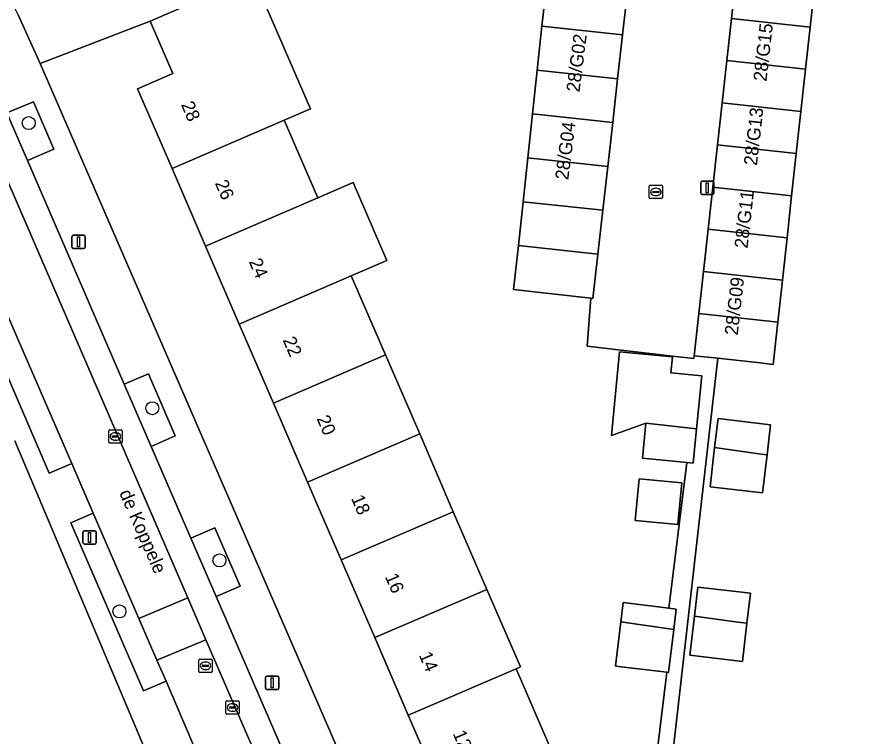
# Model space of a CAD drawing. Extents: x 162026 to 163502, y 387295 to 388169.
# Drawn here: x 162167.8 to 162230.9, y 387554 to 387608.3 of the extents above; entities that cross this region are included whole.
import ezdxf

# ---------------------------------------------------------------- set-up
doc = ezdxf.new("R2010")
doc.units = 0
for name, color, linetype in [('IMGEO_Boom', 7, 'Continuous'), ('IMGEO_Erf', 7, 'Continuous'), ('IMGEO_Groenvoorziening', 7, 'Continuous'), ('IMGEO_Kolk', 7, 'Continuous'), ('IMGEO_Lichtmast', 7, 'Continuous'), ('IMGEO_Openbare_ruimte_label', 7, 'Continuous'), ('IMGEO_Pand', 7, 'Continuous'), ('IMGEO_Pand_nummerreeks', 7, 'Continuous'), ('IMGEO_Parkeervlak_open', 7, 'Continuous'), ('IMGEO_Rijbaan_lokaal_open', 7, 'Continuous'), ('IMGEO_Rioolput', 7, 'Continuous'), ('IMGEO_Voetpad_open', 7, 'Continuous')]:
    doc.layers.add(name, color=color, linetype=linetype)

msp = doc.modelspace()

# ---------------------------------------------------------------- linework, layer by layer
at = {"layer": 'IMGEO_Boom'}
for centre in [(162168.747, 387600.231), (162178.065, 387578.73), (162183.126, 387567.244), (162175.583, 387563.398)]:
    msp.add_circle(centre, 0.489, dxfattribs=at)
at = {"layer": 'IMGEO_Erf'}
for points in [[(162240.54, 387631.778), (162230.472, 387632.88), (162230.124, 387629.722), (162229.773, 387626.543), (162229.422, 387623.364), (162229.071, 387620.185), (162228.72, 387617.006), (162228.37, 387613.827), (162228.019, 387610.647), (162227.668, 387607.468), (162227.317, 387604.289), (162226.966, 387601.11), (162226.616, 387597.931), (162226.265, 387594.752), (162225.914, 387591.573), (162225.563, 387588.394), (162225.212, 387585.214), (162224.861, 387582.031), (162223.896, 387582.138), (162220.71, 387582.491), (162216.94, 387549.426)], [(162185.674, 387611.291), (162189.987, 387601.306), (162188.001, 387600.448), (162190.532, 387594.591), (162193.203, 387595.743), (162195.737, 387589.877), (162193.066, 387588.725), (162195.647, 387582.748), (162198.221, 387576.79), (162200.755, 387570.924), (162203.289, 387565.057), (162205.815, 387559.209), (162205.496, 387559.072), (162210.608, 387547.253)], [(162215.593, 387548.453), (162216.856, 387558.813), (162212.99, 387559.284), (162213.396, 387562.616), (162213.573, 387564.068), (162217.015, 387563.648), (162218.354, 387574.629), (162215.021, 387574.957), (162215.281, 387577.595), (162212.679, 387576.674), (162213.296, 387582.99), (162217.277, 387582.6), (162217.284, 387582.658), (162210.842, 387583.401), (162211.127, 387587.022), (162205.304, 387587.68), (162205.66, 387590.99), (162206.016, 387594.299), (162206.372, 387597.609), (162206.727, 387600.919), (162207.083, 387604.229), (162207.439, 387607.538), (162207.795, 387610.848)], [(162199.955, 387549.558), (162197.353, 387555.582), (162194.827, 387561.43), (162192.297, 387567.287), (162189.763, 387573.153), (162187.193, 387579.101), (162184.612, 387585.078), (162182.078, 387590.944), (162179.548, 387596.801), (162176.945, 387602.826), (162179.598, 387603.972), (162177.889, 387607.929), (162169.617, 387604.73), (162206.97, 387518.594)], [(162192.733, 387518.666), (162181.749, 387542.942), (162167.692, 387576.257)]]:
    msp.add_lwpolyline(points, dxfattribs=at)
for points in [[(162224.672, 387577.479), (162224.406, 387575.221), (162224.067, 387572.335), (162220.109, 387572.801), (162220.457, 387575.761), (162220.714, 387577.945)], [(162214.772, 387573.405), (162217.984, 387573.089), (162217.675, 387569.947), (162214.462, 387570.263)], [(162223.159, 387564.771), (162222.894, 387562.52), (162222.554, 387559.627), (162218.596, 387560.092), (162218.944, 387563.05), (162219.201, 387565.236)]]:
    msp.add_lwpolyline(points, close=True, dxfattribs=at)
at = {"layer": 'IMGEO_Groenvoorziening'}
for points in [[(162167.091, 387600.998), (162168.662, 387597.412), (162170.641, 387598.257), (162169.112, 387601.843)], [(162167.139, 387585.739), (162165.454, 387585.008), (162170.297, 387573.838), (162171.986, 387574.558)], [(162175.938, 387580.549), (162177.973, 387575.852), (162179.793, 387576.634), (162177.764, 387581.326)], [(162173.611, 387570.804), (162171.912, 387570.09), (162177.391, 387557.416), (162179.11, 387558.145), (162178.416, 387559.712), (162177.044, 387562.862)], [(162180.971, 387568.927), (162182.887, 387564.514), (162184.692, 387565.294), (162182.789, 387569.707)]]:
    msp.add_lwpolyline(points, close=True, dxfattribs=at)
at = {"layer": 'IMGEO_Kolk'}
for p, q in [((162215.53, 387594.615), (162215.53, 387595.467)), ((162215.605, 387595.541), (162216.457, 387595.541)), ((162216.018, 387595.321), (162216.043, 387595.321)), ((162216.531, 387595.467), (162216.531, 387594.615)), ((162216.457, 387594.541), (162215.605, 387594.541)), ((162215.789, 387595.035), (162215.789, 387595.047)), ((162216.227, 387594.998), (162215.829, 387594.998)), ((162215.832, 387595.084), (162216.23, 387595.084)), ((162216.041, 387594.761), (162216.016, 387594.761)), ((162216.273, 387595.047), (162216.273, 387595.035)), ((162174.783, 387576.171), (162174.783, 387577.023)), ((162174.858, 387577.097), (162175.71, 387577.097)), ((162175.271, 387576.877), (162175.296, 387576.877)), ((162175.784, 387577.023), (162175.784, 387576.171)), ((162175.042, 387576.591), (162175.042, 387576.603)), ((162175.48, 387576.554), (162175.082, 387576.554)), ((162175.085, 387576.64), (162175.483, 387576.64)), ((162175.294, 387576.317), (162175.269, 387576.317)), ((162175.526, 387576.603), (162175.526, 387576.591)), ((162175.71, 387576.097), (162174.858, 387576.097)), ((162183.616, 387555.725), (162183.616, 387556.577)), ((162183.691, 387556.651), (162184.543, 387556.651)), ((162183.875, 387556.145), (162183.875, 387556.157)), ((162184.313, 387556.108), (162183.915, 387556.108)), ((162183.918, 387556.194), (162184.316, 387556.194)), ((162184.104, 387556.431), (162184.129, 387556.431)), ((162184.359, 387556.157), (162184.359, 387556.145)), ((162184.617, 387556.577), (162184.617, 387555.725)), ((162184.543, 387555.651), (162183.691, 387555.651)), ((162184.127, 387555.871), (162184.102, 387555.871))]:
    msp.add_line(p, q, dxfattribs=at)
for points in [[(162215.53, 387594.615), (162215.53, 387595.467)], [(162215.605, 387595.541), (162216.457, 387595.541)], [(162216.531, 387595.467), (162216.531, 387594.615)], [(162216.457, 387594.541), (162215.605, 387594.541)], [(162174.783, 387576.171), (162174.783, 387577.023)], [(162174.858, 387577.097), (162175.71, 387577.097)], [(162175.784, 387577.023), (162175.784, 387576.171)], [(162175.71, 387576.097), (162174.858, 387576.097)], [(162183.616, 387555.725), (162183.616, 387556.577)], [(162183.691, 387556.651), (162184.543, 387556.651)], [(162184.617, 387556.577), (162184.617, 387555.725)], [(162184.543, 387555.651), (162183.691, 387555.651)]]:
    msp.add_lwpolyline(points, dxfattribs=at)
for centre, radius, start, end in [((162215.607, 387595.465), 0.0765, 91.55205, 178.44795), ((162215.607, 387595.465), 0.0765, 91.55205, 178.44795), ((162216.455, 387595.465), 0.0765, 1.55205, 88.44795), ((162216.455, 387595.465), 0.0765, 1.55205, 88.44795), ((162215.607, 387594.617), 0.0765, 181.55205, 268.44795), ((162215.607, 387594.617), 0.0765, 181.55205, 268.44795), ((162215.829, 387595.044), 0.0403, 85.87752, 175.75265), ((162215.826, 387595.034), 0.0366, 178.93798, 274.71019), ((162216.23, 387595.041), 0.043, 264.86636, 352.45326), ((162216.234, 387595.046), 0.0386, 1.73085, 96.63898), ((162216.455, 387594.617), 0.0765, 271.55205, 358.44795), ((162216.455, 387594.617), 0.0765, 271.55205, 358.44795), ((162174.86, 387577.021), 0.0765, 91.55205, 178.44795), ((162174.86, 387577.021), 0.0765, 91.55205, 178.44795), ((162175.708, 387577.021), 0.0765, 1.55205, 88.44795), ((162175.708, 387577.021), 0.0765, 1.55205, 88.44795), ((162175.082, 387576.6), 0.0403, 85.87752, 175.75265), ((162175.079, 387576.59), 0.0366, 178.93798, 274.71019), ((162175.483, 387576.597), 0.043, 264.86636, 352.45326), ((162175.487, 387576.602), 0.0386, 1.73085, 96.63898), ((162174.86, 387576.173), 0.0765, 181.55205, 268.44795), ((162174.86, 387576.173), 0.0765, 181.55205, 268.44795), ((162175.708, 387576.173), 0.0765, 271.55205, 358.44795), ((162175.708, 387576.173), 0.0765, 271.55205, 358.44795), ((162183.693, 387556.575), 0.0765, 91.55205, 178.44795), ((162183.693, 387556.575), 0.0765, 91.55205, 178.44795), ((162183.915, 387556.154), 0.0403, 85.87752, 175.75265), ((162183.912, 387556.144), 0.0366, 178.93798, 274.71019), ((162184.316, 387556.151), 0.043, 264.86636, 352.45326), ((162184.32, 387556.156), 0.0386, 1.73085, 96.63898), ((162184.541, 387556.575), 0.0765, 1.55205, 88.44795), ((162184.541, 387556.575), 0.0765, 1.55205, 88.44795), ((162183.693, 387555.727), 0.0765, 181.55205, 268.44795), ((162183.693, 387555.727), 0.0765, 181.55205, 268.44795), ((162184.541, 387555.727), 0.0765, 271.55205, 358.44795), ((162184.541, 387555.727), 0.0765, 271.55205, 358.44795)]:
    msp.add_arc(centre, radius, start, end, dxfattribs=at)
for centre, major_axis, ratio, start_param, end_param in [((162216.017, 387595.041), (-0.387, 0.002), 0.722429, 4.712389, 7.853982), ((162216.042, 387595.041), (-0.39, 0.002), 0.717154, 1.570796, 4.712389), ((162175.27, 387576.597), (-0.387, 0.002), 0.722429, 4.712389, 7.853982), ((162175.295, 387576.597), (-0.39, 0.002), 0.717154, 1.570796, 4.712389), ((162184.103, 387556.151), (-0.387, 0.002), 0.722429, 4.712389, 7.853982), ((162184.128, 387556.151), (-0.39, 0.002), 0.717154, 1.570796, 4.712389)]:
    msp.add_ellipse(centre, major_axis=major_axis, ratio=ratio, start_param=start_param, end_param=end_param, dxfattribs=at)
at = {"layer": 'IMGEO_Lichtmast'}
for p, q in [((162219.509, 387595.854), (162220.299, 387595.854)), ((162220.299, 387595.854), (162219.509, 387595.854)), ((162219.409, 387594.954), (162219.409, 387595.754)), ((162219.409, 387595.754), (162219.409, 387594.954)), ((162220.399, 387595.754), (162220.399, 387594.954)), ((162220.399, 387594.954), (162220.399, 387595.754)), ((162220.299, 387594.854), (162219.509, 387594.854)), ((162219.509, 387594.854), (162220.299, 387594.854)), ((162172.006, 387590.877), (162172.006, 387591.677)), ((162172.006, 387591.677), (162172.006, 387590.877)), ((162172.106, 387591.777), (162172.896, 387591.777)), ((162172.896, 387591.777), (162172.106, 387591.777)), ((162172.996, 387591.677), (162172.996, 387590.877)), ((162172.996, 387590.877), (162172.996, 387591.677)), ((162172.896, 387590.777), (162172.106, 387590.777)), ((162172.106, 387590.777), (162172.896, 387590.777)), ((162172.834, 387568.582), (162172.834, 387569.382)), ((162172.834, 387569.382), (162172.834, 387568.582)), ((162172.934, 387569.482), (162173.724, 387569.482)), ((162173.724, 387569.482), (162172.934, 387569.482)), ((162173.824, 387569.382), (162173.824, 387568.582)), ((162173.824, 387568.582), (162173.824, 387569.382)), ((162173.724, 387568.482), (162172.934, 387568.482)), ((162172.934, 387568.482), (162173.724, 387568.482)), ((162186.604, 387557.617), (162186.604, 387558.417)), ((162186.604, 387558.417), (162186.604, 387557.617)), ((162186.704, 387558.517), (162187.494, 387558.517)), ((162187.494, 387558.517), (162186.704, 387558.517)), ((162187.594, 387558.417), (162187.594, 387557.617)), ((162187.594, 387557.617), (162187.594, 387558.417)), ((162187.494, 387557.517), (162186.704, 387557.517)), ((162186.704, 387557.517), (162187.494, 387557.517))]:
    msp.add_line(p, q, dxfattribs=at)
for points in [[(162219.829, 387595.729), (162219.979, 387595.729), (162219.979, 387594.979), (162219.829, 387594.979), (162219.829, 387595.729)], [(162172.426, 387591.652), (162172.576, 387591.652), (162172.576, 387590.902), (162172.426, 387590.902), (162172.426, 387591.652)], [(162173.254, 387569.357), (162173.404, 387569.357), (162173.404, 387568.607), (162173.254, 387568.607), (162173.254, 387569.357)], [(162187.024, 387558.392), (162187.174, 387558.392), (162187.174, 387557.642), (162187.024, 387557.642), (162187.024, 387558.392)]]:
    msp.add_lwpolyline(points, dxfattribs=at)
for centre, start, end in [((162219.509, 387595.754), 90, 180), ((162219.509, 387595.754), 90, 180), ((162220.299, 387595.754), 0, 90), ((162220.299, 387595.754), 360, 90), ((162219.509, 387594.954), 180, 270), ((162219.509, 387594.954), 180, 270), ((162220.299, 387594.954), 270, 0), ((162220.299, 387594.954), 270, 0), ((162172.106, 387591.677), 90, 180), ((162172.106, 387591.677), 90, 180), ((162172.896, 387591.677), 0, 90), ((162172.896, 387591.677), 360, 90), ((162172.106, 387590.877), 180, 270), ((162172.106, 387590.877), 180, 270), ((162172.896, 387590.877), 270, 0), ((162172.896, 387590.877), 270, 0), ((162172.934, 387569.382), 90, 180), ((162172.934, 387569.382), 90, 180), ((162173.724, 387569.382), 0, 90), ((162173.724, 387569.382), 360, 90), ((162172.934, 387568.582), 180, 270), ((162172.934, 387568.582), 180, 270), ((162173.724, 387568.582), 270, 0), ((162173.724, 387568.582), 270, 0), ((162186.704, 387558.417), 90, 180), ((162186.704, 387558.417), 90, 180), ((162187.494, 387558.417), 0, 90), ((162187.494, 387558.417), 360, 90), ((162186.704, 387557.617), 180, 270), ((162186.704, 387557.617), 180, 270), ((162187.494, 387557.617), 270, 0), ((162187.494, 387557.617), 270, 0)]:
    msp.add_arc(centre, 0.1, start, end, dxfattribs=at)
at = {"layer": 'IMGEO_Pand'}
for points in [[(162177.889, 387607.929), (162179.598, 387603.972), (162176.945, 387602.826), (162179.548, 387596.801), (162188.001, 387600.448), (162189.987, 387601.306), (162185.674, 387611.291)], [(162221.722, 387608.122), (162227.668, 387607.468), (162228.019, 387610.647), (162222.072, 387611.301)], [(162213.89, 387610.18), (162207.795, 387610.848), (162207.439, 387607.538), (162213.518, 387606.885)], [(162221.373, 387604.943), (162227.317, 387604.289), (162227.668, 387607.468), (162221.722, 387608.122)], [(162213.518, 387606.885), (162207.439, 387607.538), (162207.083, 387604.229), (162213.144, 387603.577)], [(162221.023, 387601.764), (162226.966, 387601.11), (162227.317, 387604.289), (162221.373, 387604.943)], [(162213.144, 387603.577), (162207.083, 387604.229), (162206.727, 387600.919), (162212.771, 387600.269)], [(162220.674, 387598.584), (162226.616, 387597.931), (162226.966, 387601.11), (162221.023, 387601.764)], [(162212.771, 387600.269), (162206.727, 387600.919), (162206.372, 387597.609), (162212.397, 387596.961)], [(162179.548, 387596.801), (162182.078, 387590.944), (162190.532, 387594.591), (162188.001, 387600.448)], [(162220.324, 387595.405), (162226.265, 387594.752), (162226.616, 387597.931), (162220.674, 387598.584)], [(162212.397, 387596.961), (162206.372, 387597.609), (162206.016, 387594.299), (162212.024, 387593.653)], [(162190.532, 387594.591), (162182.078, 387590.944), (162184.612, 387585.078), (162193.066, 387588.725), (162195.737, 387589.877), (162193.203, 387595.743)], [(162219.975, 387592.226), (162225.914, 387591.573), (162226.265, 387594.752), (162220.324, 387595.405)], [(162212.024, 387593.653), (162206.016, 387594.299), (162205.66, 387590.99), (162211.65, 387590.346)], [(162219.625, 387589.046), (162225.563, 387588.394), (162225.914, 387591.573), (162219.975, 387592.226)], [(162211.273, 387587.006), (162211.65, 387590.346), (162205.66, 387590.99), (162205.304, 387587.68), (162211.127, 387587.022)], [(162219.276, 387585.867), (162225.212, 387585.214), (162225.563, 387588.394), (162219.625, 387589.046)], [(162184.612, 387585.078), (162187.193, 387579.101), (162195.647, 387582.748), (162193.066, 387588.725)], [(162225.212, 387585.214), (162219.276, 387585.867), (162218.926, 387582.688), (162220.71, 387582.491), (162223.896, 387582.138), (162224.861, 387582.031)], [(162187.193, 387579.101), (162189.763, 387573.153), (162198.221, 387576.79), (162195.647, 387582.748)], [(162219.086, 387577.164), (162219.48, 387581.179), (162217.161, 387581.407), (162217.277, 387582.6), (162213.296, 387582.99), (162212.679, 387576.674), (162215.281, 387577.595)], [(162219.086, 387577.164), (162215.281, 387577.595), (162215.021, 387574.957), (162218.354, 387574.629), (162218.832, 387574.582)], [(162224.406, 387575.221), (162224.672, 387577.479), (162220.714, 387577.945), (162220.457, 387575.761), (162223.957, 387575.269)], [(162200.755, 387570.924), (162198.221, 387576.79), (162189.763, 387573.153), (162192.297, 387567.287)], [(162223.957, 387575.269), (162220.457, 387575.761), (162220.109, 387572.801), (162224.067, 387572.335), (162224.406, 387575.221)], [(162214.462, 387570.263), (162217.675, 387569.947), (162217.984, 387573.089), (162214.772, 387573.405)], [(162192.297, 387567.287), (162194.827, 387561.43), (162203.289, 387565.057), (162200.755, 387570.924)], [(162205.815, 387559.209), (162203.289, 387565.057), (162194.827, 387561.43), (162197.353, 387555.582), (162205.496, 387559.072)], [(162222.894, 387562.52), (162223.159, 387564.771), (162219.201, 387565.236), (162218.944, 387563.05), (162222.207, 387562.599)], [(162217.567, 387563.581), (162217.015, 387563.648), (162213.573, 387564.068), (162213.396, 387562.616), (162217.38, 387562.043)], [(162222.207, 387562.599), (162218.944, 387563.05), (162218.596, 387560.092), (162222.554, 387559.627), (162222.894, 387562.52)], [(162217.38, 387562.043), (162213.396, 387562.616), (162212.99, 387559.284), (162216.856, 387558.813), (162216.985, 387558.797)], [(162205.496, 387559.072), (162197.353, 387555.582), (162199.955, 387549.558), (162200.323, 387549.715), (162202.279, 387545.186), (162209.913, 387547.081), (162210.608, 387547.253)]]:
    msp.add_lwpolyline(points, close=True, dxfattribs=at)
at = {"layer": 'IMGEO_Parkeervlak_open'}
msp.add_lwpolyline([(162182.887, 387564.514), (162180.971, 387568.927), (162177.973, 387575.852), (162175.938, 387580.549), (162168.662, 387597.412), (162167.091, 387600.998), (162167.011, 387601.185), (162165.168, 387600.429), (162180.74, 387564.422), (162182.107, 387561.26), (162188.57, 387546.317), (162190.414, 387547.086), (162188.504, 387551.502)], close=True, dxfattribs=at)
at = {"layer": 'IMGEO_Rijbaan_lokaal_open'}
for points in [[(162167.945, 387608.39), (162169.617, 387604.73), (162177.889, 387607.929), (162185.674, 387611.291)], [(162213.89, 387610.18), (162213.518, 387606.885), (162213.144, 387603.577), (162212.771, 387600.269), (162212.397, 387596.961), (162212.024, 387593.653), (162211.65, 387590.346), (162211.273, 387587.006), (162211.127, 387587.022), (162210.842, 387583.401), (162217.284, 387582.658), (162218.894, 387582.472), (162218.926, 387582.688), (162219.276, 387585.867), (162219.625, 387589.046), (162219.975, 387592.226), (162220.324, 387595.405), (162220.674, 387598.584), (162221.023, 387601.764), (162221.373, 387604.943), (162221.722, 387608.122), (162222.072, 387611.301)], [(162157.496, 387608.095), (162161.151, 387599.629), (162163.025, 387595.286), (162167.139, 387585.739), (162171.986, 387574.558), (162173.611, 387570.804), (162177.044, 387562.862), (162180.74, 387564.422), (162165.168, 387600.429), (162161.658, 387608.545)], [(162202.905, 387512.975), (162201.516, 387516.321), (162199.227, 387521.644), (162192.35, 387537.558), (162188.57, 387546.317), (162182.107, 387561.26), (162178.416, 387559.712), (162179.11, 387558.145), (162181.87, 387551.664), (162188.019, 387537.445), (162191.081, 387530.363), (162197.664, 387515.178), (162197.789, 387514.889), (162198.944, 387512.277)]]:
    msp.add_lwpolyline(points, dxfattribs=at)
msp.add_lwpolyline([(162180.74, 387564.422), (162177.044, 387562.862), (162178.416, 387559.712), (162182.107, 387561.26)], close=True, dxfattribs=at)
at = {"layer": 'IMGEO_Rioolput'}
for p, q in [((162181.572, 387558.875), (162181.572, 387559.727)), ((162181.647, 387559.801), (162182.499, 387559.801)), ((162181.831, 387559.295), (162181.831, 387559.307)), ((162182.269, 387559.258), (162181.871, 387559.258)), ((162181.874, 387559.344), (162182.272, 387559.344)), ((162182.06, 387559.581), (162182.085, 387559.581)), ((162182.315, 387559.307), (162182.315, 387559.295)), ((162182.573, 387559.727), (162182.573, 387558.875)), ((162182.499, 387558.801), (162181.647, 387558.801)), ((162182.083, 387559.021), (162182.058, 387559.021))]:
    msp.add_line(p, q, dxfattribs=at)
for points in [[(162181.572, 387558.875), (162181.572, 387559.727)], [(162181.647, 387559.801), (162182.499, 387559.801)], [(162182.573, 387559.727), (162182.573, 387558.875)], [(162182.499, 387558.801), (162181.647, 387558.801)]]:
    msp.add_lwpolyline(points, dxfattribs=at)
for centre, radius, start, end in [((162181.649, 387559.725), 0.0765, 91.55205, 178.44795), ((162181.649, 387559.725), 0.0765, 91.55205, 178.44795), ((162181.871, 387559.304), 0.0403, 85.87752, 175.75265), ((162181.868, 387559.294), 0.0366, 178.93798, 274.71019), ((162182.272, 387559.301), 0.043, 264.86636, 352.45326), ((162182.276, 387559.306), 0.0386, 1.73085, 96.63898), ((162182.497, 387559.725), 0.0765, 1.55205, 88.44795), ((162182.497, 387559.725), 0.0765, 1.55205, 88.44795), ((162181.649, 387558.877), 0.0765, 181.55205, 268.44795), ((162181.649, 387558.877), 0.0765, 181.55205, 268.44795), ((162182.497, 387558.877), 0.0765, 271.55205, 358.44795), ((162182.497, 387558.877), 0.0765, 271.55205, 358.44795)]:
    msp.add_arc(centre, radius, start, end, dxfattribs=at)
for centre, major_axis, ratio, start_param, end_param in [((162182.059, 387559.301), (-0.387, 0.002), 0.722429, 4.712389, 7.853982), ((162182.084, 387559.301), (-0.39, 0.002), 0.717154, 1.570796, 4.712389)]:
    msp.add_ellipse(centre, major_axis=major_axis, ratio=ratio, start_param=start_param, end_param=end_param, dxfattribs=at)
at = {"layer": 'IMGEO_Voetpad_open'}
for points in [[(162206.97, 387518.594), (162169.617, 387604.73), (162167.945, 387608.39), (162167.679, 387608.941), (162167.267, 387609.969), (162166.949, 387611.031), (162166.875, 387611.347), (162166.727, 387612.116), (162166.603, 387613.218), (162166.477, 387613.998), (162166.652, 387615.431), (162167.307, 387621.991), (162166.913, 387622.036), (162167.629, 387628.415)], [(162163.509, 387609.313), (162167.011, 387601.185), (162167.091, 387600.998), (162169.112, 387601.843), (162170.641, 387598.257), (162168.662, 387597.412), (162175.938, 387580.549), (162177.764, 387581.326), (162179.793, 387576.634), (162177.973, 387575.852), (162180.971, 387568.927), (162182.789, 387569.707), (162184.692, 387565.294), (162182.887, 387564.514), (162188.504, 387551.502)], [(162179.11, 387558.145), (162177.391, 387557.416), (162171.912, 387570.09), (162173.611, 387570.804), (162171.986, 387574.558), (162170.297, 387573.838), (162165.454, 387585.008), (162167.139, 387585.739), (162163.025, 387595.286), (162161.041, 387594.389), (162159.155, 387598.767), (162161.151, 387599.629), (162157.496, 387608.095)], [(162216.94, 387549.426), (162220.71, 387582.491), (162218.926, 387582.688), (162218.894, 387582.472), (162217.284, 387582.658), (162217.277, 387582.6), (162217.161, 387581.407), (162219.48, 387581.179), (162219.086, 387577.164), (162218.832, 387574.582), (162218.354, 387574.629), (162217.015, 387563.648), (162217.567, 387563.581), (162217.38, 387562.043), (162216.985, 387558.797), (162216.856, 387558.813), (162215.593, 387548.453)], [(162167.692, 387576.257), (162181.749, 387542.942), (162192.733, 387518.666)], [(162193.815, 387519.203), (162192.494, 387522.609), (162189.415, 387529.605), (162191.081, 387530.363), (162188.019, 387537.445), (162186.337, 387536.654), (162180.202, 387550.886), (162181.87, 387551.664), (162179.11, 387558.145)]]:
    msp.add_lwpolyline(points, dxfattribs=at)

# ---------------------------------------------------------------- texts
at = {"layer": 'IMGEO_Openbare_ruimte_label'}
msp.add_text('de Koppele', height=1, rotation=293.56707, dxfattribs=at).set_placement((162175.552, 387572.344))
at = {"layer": 'IMGEO_Pand_nummerreeks'}
for s, rotation, p in [('28/G15', 83.53482, (162224.363, 387603.343)), ('28/G02', 82.70305, (162210.266, 387602.529)), ('28', 293.36273, (162180.211, 387601.623)), ('28/G13', 83.53482, (162223.644, 387596.992)), ('28/G04', 82.70305, (162209.419, 387595.909)), ('26', 293.36273, (162182.765, 387595.706)), ('28/G11', 83.53482, (162222.936, 387590.751)), ('24', 293.36501, (162185.323, 387589.787)), ('28/G09', 83.53482, (162222.194, 387584.197)), ('22', 293.36273, (162187.878, 387583.872)), ('20', 293.36273, (162190.437, 387577.948)), ('18', 293.36273, (162193.03, 387571.945)), ('16', 293.36273, (162195.585, 387566.03)), ('14', 293.36273, (162198.141, 387560.111)), ('12', 293.36273, (162200.697, 387554.195))]:
    msp.add_text(s, height=1, rotation=rotation, dxfattribs=at).set_placement(p)

doc.saveas('drawing.dxf')
